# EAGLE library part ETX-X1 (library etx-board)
PCI-Bus, USB, Audio ETX Board Connector 100 Pos. Source: www.kontron.com/techlib/whitepapers/etx_spec.pdf
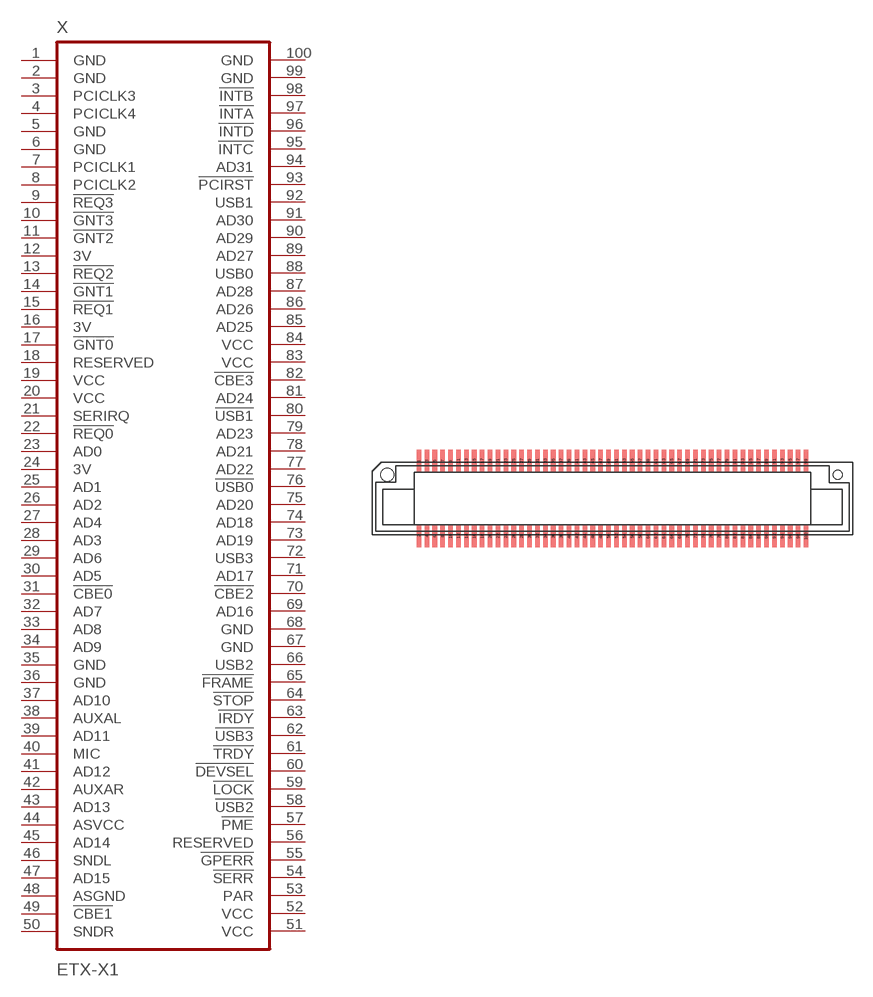
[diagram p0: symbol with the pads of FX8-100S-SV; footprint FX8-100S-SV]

Designator prefix X

## ETX-X1  [FX8-100S-SV]
1  GND  pwr
2  GND  pwr
3  PCICLK3
4  PCICLK4
5  GND  pwr
6  GND  pwr
7  PCICLK1
8  PCICLK2
9  !REQ3
10  !GNT3
11  !GNT2
12  3V  pwr
13  !REQ2
14  !GNT1
15  !REQ1
16  3V  pwr
17  !GNT0
18  RESERVED
19  VCC  pwr
20  VCC  pwr
21  SERIRQ
22  !REQ0
23  AD0
24  3V  pwr
25  AD1
26  AD2
27  AD4
28  AD3
29  AD6
30  AD5
31  !CBE0
32  AD7
33  AD8
34  AD9
35  GND  pwr
36  GND
37  AD10
38  AUXAL
39  AD11
40  MIC
41  AD12
42  AUXAR
43  AD13
44  ASVCC  pwr
45  AD14
46  SNDL
47  AD15
48  ASGND  pwr
49  !CBE1
50  SNDR
51  VCC  pwr
52  VCC  pwr
53  PAR
54  !SERR
55  !GPERR
56  RESERVED
57  !PME
58  !USB2
59  !LOCK
60  !DEVSEL
61  !TRDY
62  !USB3
63  !IRDY
64  !STOP
65  !FRAME
66  USB2
67  GND  pwr
68  GND  pwr
69  AD16
70  !CBE2
71  AD17
72  USB3
73  AD19
74  AD18
75  AD20
76  !USB0
77  AD22
78  AD21
79  AD23
80  !USB1
81  AD24
82  !CBE3
83  VCC  pwr
84  VCC  pwr
85  AD25
86  AD26
87  AD28
88  USB0
89  AD27
90  AD29
91  AD30
92  USB1
93  !PCIRST
94  AD31
95  !INTC
96  !INTD
97  !INTA
98  !INTB
99  GND  pwr
100  GND  pwr

## Footprint FX8-100S-SV (pad centres in mm)
HIROSE - ETX Board Connector 100 Pos. Source: www.hirose.co.jp/cataloge_hp/e57800016.pdf www.kontron.com/techlib/whitepapers/etx_spec.pdf
smd 0.35 x 1.7: 1 -14.7,2.85; 2 -14.7,-2.85; 3 -14.1,2.85; 4 -14.1,-2.85; 5 -13.5,2.85; 6 -13.5,-2.85; 7 -12.9,2.85; 8 -12.9,-2.85; 9 -12.3,2.85; 10 -12.3,-2.85; 11 -11.7,2.85; 12 -11.7,-2.85; 13 -11.1,2.85; 14 -11.1,-2.85; 15 -10.5,2.85; 16 -10.5,-2.85; 17 -9.9,2.85; 18 -9.9,-2.85; 19 -9.3,2.85; 20 -9.3,-2.85; 21 -8.7,2.85; 22 -8.7,-2.85; 23 -8.1,2.85; 24 -8.1,-2.85; 25 -7.5,2.85; 26 -7.5,-2.85; 27 -6.9,2.85; 28 -6.9,-2.85; 29 -6.3,2.85; 30 -6.3,-2.85; 31 -5.7,2.85; 32 -5.7,-2.85; 33 -5.1,2.85; 34 -5.1,-2.85; 35 -4.5,2.85; 36 -4.5,-2.85; 37 -3.9,2.85; 38 -3.9,-2.85; 39 -3.3,2.85; 40 -3.3,-2.85; 41 -2.7,2.85; 42 -2.7,-2.85; 43 -2.1,2.85; 44 -2.1,-2.85; 45 -1.5,2.85; 46 -1.5,-2.85; 47 -0.9,2.85; 48 -0.9,-2.85; 49 -0.3,2.85; 50 -0.3,-2.85; 51 0.3,2.85; 52 0.3,-2.85; 53 0.9,2.85; 54 0.9,-2.85; 55 1.5,2.85; 56 1.5,-2.85; 57 2.1,2.85; 58 2.1,-2.85; 59 2.7,2.85; 60 2.7,-2.85; 61 3.3,2.85; 62 3.3,-2.85; 63 3.9,2.85; 64 3.9,-2.85; 65 4.5,2.85; 66 4.5,-2.85; 67 5.1,2.85; 68 5.1,-2.85; 69 5.7,2.85; 70 5.7,-2.85; 71 6.3,2.85; 72 6.3,-2.85; 73 6.9,2.85; 74 6.9,-2.85; 75 7.5,2.85; 76 7.5,-2.85; 77 8.1,2.85; 78 8.1,-2.85; 79 8.7,2.85; 80 8.7,-2.85; 81 9.3,2.85; 82 9.3,-2.85; 83 9.9,2.85; 84 9.9,-2.85; 85 10.5,2.85; 86 10.5,-2.85; 87 11.1,2.85; 88 11.1,-2.85; 89 11.7,2.85; 90 11.7,-2.85; 91 12.3,2.85; 92 12.3,-2.85; 93 12.9,2.85; 94 12.9,-2.85; 95 13.5,2.85; 96 13.5,-2.85; 97 14.1,2.85; 98 14.1,-2.85; 99 14.7,2.85; 100 14.7,-2.85
hole 1 at -17.1,1.8
hole 0.7 at 17.1,1.8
